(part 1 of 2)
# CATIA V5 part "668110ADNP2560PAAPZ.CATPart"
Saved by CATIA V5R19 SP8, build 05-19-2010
Part number: 668110 ADNP-25-60-P-A---A-P-(Z)
Definition: Cadenas PARTsolutions
Description: NT
Property "NN": "ADNP-A-P-(Z)"
Property "NT": "Normzylinder"
Property "NB": "668110 ADNP-25-60-P-A---A-P-(Z)"
Property "NBSYN": "$TNR. $TYP.-$HUB.-$ED.---A-P-(Z)"
Property "LINA": "668110 ADNP-25-60-P-A---A-P-(Z)"
Property "TNR": "668110"
Property "TYP": "ADNP-25"
Property "AUSF": "ADNP"
Property "KDM": "25"
Property "BG": "19.500"
Property "VERS": "1"
Property "HUB": "60.00000"
Property "THC": "'A','I'"
Property "ED": "P-A"
Property "A": "16.000"
Property "A1": "16.000"
Property "AF": "14.000"
Property "AF1": "0.000"
Property "AF2": "12.000"
Property "AF3": "14.000"
Property "B": "22.000"
Property "B1": "18.000"
Property "BG1": "15.000"
Property "D1": "9.000"
Property "D2": "9.000"
Property "D3": "4.100"
Property "D4": "14.000"
Property "D5": "6.000"
Property "D6": "M5"
Property "D7": "5.000"
Property "D8": "3.800"
Property "D9": "6.000"
Property "E": "39.500"
Property "EE": "M5"
Property "EEN": "5.000"
Property "EE1": "M5"
Property "J": "12.000"
Property "J1": "2.600"
Property "J11": "2.600"
Property "J2": "0.000"
Property "KF": "10-32 UNF-2B"
Property "KF1": "-"
Property "KF2": "10-32 UNF-2B"
Property "KF3": "10-32 UNF-2B"
Property "KK": "5/16-24 UNF-2A"
Property "KK1": "5/16-24 UNF-2A"
Property "L1": "2.600"
Property "L2": "39.000"
Property "L3": "2.100"
Property "L4": "4.800"
Property "L5": "5.000"
Property "L6": "53.000"
Property "L7": "22.000"
Property "L8": "2.000"
Property "L9": "2.000"
Property "L10": "5.000"
Property "L11": "2.600"
Property "MF": "8.000"
Property "MM": "10.000"
Property "MM1": "10.000"
Property "PL": "6.000"
Property "RT": "M5"
Property "RTN": "5"
Property "RTNK": "4.134"
Property "SF": "11/32"
Property "SF1": "11/32"
Property "SW": "9.000"
Property "TG": "26.000"
Property "VD": "6.000"
Property "VD1": "5.200"
Property "WH": "5.700"
Property "WH1": "11.650"
Property "WL": "4.200"
Property "WL1": "4.200"
Property "Y1": "0.300"
Property "Y2": "0.500"
Property "ZJ": "44.700"
Property "ZM": "50.400"
Property "RU": "28.200"
Property "R1": "11.700"
Property "R2": "0.800"
Property "RA": "0.000"
Property "RB1": "5.400"
Property "RB2": "6.800"
Property "RT1": "3.400"
Property "DSK": "8.000"
Property "MDK": "10.000"
Property "MK": "6.000"
Property "MT": "3.000"
Property "MS": "5.000"
Property "RUB": "0.400"
Property "KFN": "6.000"
Property "KFK": "4.917"
Property "B111": "11.500"
Property "B11": "1.000"
Property "B2": "6.500"
Property "B3": "10.500"
Property "B4": "4.600"
Property "B5": "4.400"
Property "B6": "7.500"
Property "B7": "19.500"
Property "B8": "5.000"
Property "B9": "7.000"
Property "B10": "8.400"
Property "W": "0.400"
Property "S": "7.000"
Property "LA": "0.000"
Property "LA1": "0.000"
Property "LA2": "5.500"
Property "LA3": "11.000"
Property "LA31": "11.000"
Property "LA4": "0.000"
Property "LA5": "11.000"
Property "LA6": "5.500"
Property "RR": "4.100"
Property "LA7": "0.000"
Property "LA8": "0.000"
Property "LA9": "0.000"
Property "LA10": "0.000"
Property "ES": "0.000"
Property "SS": "0.000"
Property "TS": "0.000"
Property "WS": "0.000"
Property "DK": "0.000"
Property "KS": "0.000"
Property "TT": "-"
Property "R8": "-"
Property "S1": "-"
Property "S2S20": "-"
Property "Q": "-"
Property "X": "60.000"
Property "VENDOR": "FESTO"
Property "SUPPLIER": "FESTO"
Property "ARTICLENO": "NB"
Property "BOMINFO": "LINA"
Property "CREATOR": "CADENAS GmbH"
Bounding box of the stored display mesh (mm): x -19.75 to 19.75, y -19.75 to 19.75, z -99 to 0
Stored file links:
  C:\Users\Schrotter\Desktop\Neuer Ordner (2)\668110ADNP2560PAAPZ.CATPart
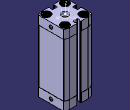
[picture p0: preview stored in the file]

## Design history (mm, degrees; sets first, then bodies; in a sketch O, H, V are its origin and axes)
AxisSystem1: origin (0, 0, 0), X (1, 0, 0), Y (0, 1, 0), Z (0, 0, 1)
Set1
  Point1: (0, 0, 0)
  Point2: (1, 0, 0)
  Point3: (0, 1, 0)
  Plane1: type 3Points, Element1 Point1, Element2 Point2, Element3 Point3
  Point4: (0, 0, -12)
  Point5: (1, 0, -12)
  Point6: (0, 1, -12)
  Plane2: type 3Points, Element1 Point4, Element2 Point5, Element3 Point6
  Point7: (0, 0, 0)
  Point8: (1, 0, 0)
  Point9: (0, 0, -1)
  Plane3: type 3Points, Element1 Point7, Element2 Point8, Element3 Point9
  Point10: (0, 0, 0)
  Point11: (1, 0, 0)
  Point12: (0, 0, -1)
  Plane4: type 3Points, Element1 Point10, Element2 Point11, Element3 Point12
  Point13: (0, 0, 0)
  Point14: (0, 0, -1)
  Point15: (0, 1, 0)
  Plane5: type 3Points, Element1 Point13, Element2 Point14, Element3 Point15
  Point16: (0, 0, 0)
  Point17: (0, 0, -1)
  Point18: (0, 1, 0)
  Plane6: type 3Points, Element1 Point16, Element2 Point17, Element3 Point18
  Point19: (13, 0, 0)
  Point20: (13, 0, -1)
  Point21: (13, 1, 0)
  Plane7: type 3Points, Element1 Point19, Element2 Point20, Element3 Point21
  Point22: (13, 0, 0)
  Point23: (13, 0, -1)
  Point24: (13, 1, 0)
  Plane8: type 3Points, Element1 Point22, Element2 Point23, Element3 Point24
  Point25: (13, 0, 0)
  Point26: (13, 0, -1)
  Point27: (13, 1, 0)
  Plane9: type 3Points, Element1 Point25, Element2 Point26, Element3 Point27
  Point28: (13, 0, 0)
  Point29: (13, 0, -1)
  Point30: (13, 1, 0)
  Plane10: type 3Points, Element1 Point28, Element2 Point29, Element3 Point30
  Point31: (-13, 0, 0)
  Point32: (-13, 0, -1)
  Point33: (-13, 1, 0)
  Plane11: type 3Points, Element1 Point31, Element2 Point32, Element3 Point33
  Point34: (-13, 0, 0)
  Point35: (-13, 0, -1)
  Point36: (-13, 1, 0)
  Plane12: type 3Points, Element1 Point34, Element2 Point35, Element3 Point36
  Point37: (-13, 0, 0)
  Point38: (-13, 0, -1)
  Point39: (-13, 1, 0)
  Plane13: type 3Points, Element1 Point37, Element2 Point38, Element3 Point39
  Point40: (-13, 0, 0)
  Point41: (-13, 0, -1)
  Point42: (-13, 1, 0)
  Plane14: type 3Points, Element1 Point40, Element2 Point41, Element3 Point42
  Point43: (-13, 0, 0)
  Point44: (-13, 0, -1)
  Point45: (-13, 1, 0)
  Plane15: type 3Points, Element1 Point43, Element2 Point44, Element3 Point45
  Point46: (-13, 0, 0)
  Point47: (-13, 0, -1)
  Point48: (-13, 1, 0)
  Plane16: type 3Points, Element1 Point46, Element2 Point47, Element3 Point48
  Point49: (13, 0, 0)
  Point50: (13, 0, -1)
  Point51: (13, 1, 0)
  Plane17: type 3Points, Element1 Point49, Element2 Point50, Element3 Point51
  Point52: (13, 0, 0)
  Point53: (13, 0, -1)
  Point54: (13, 1, 0)
  Plane18: type 3Points, Element1 Point52, Element2 Point53, Element3 Point54
  Point55: (-13, 0, 0)
  Point56: (-13, 0, -1)
  Point57: (-13, 1, 0)
  Plane19: type 3Points, Element1 Point55, Element2 Point56, Element3 Point57
  Point58: (-13, 0, 0)
  Point59: (-13, 0, -1)
  Point60: (-13, 1, 0)
  Plane20: type 3Points, Element1 Point58, Element2 Point59, Element3 Point60
  Point61: (13, 0, 0)
  Point62: (13, 0, -1)
  Point63: (13, 1, 0)
  Plane21: type 3Points, Element1 Point61, Element2 Point62, Element3 Point63
  Point64: (13, 0, 0)
  Point65: (13, 0, -1)
  Point66: (13, 1, 0)
  Plane22: type 3Points, Element1 Point64, Element2 Point65, Element3 Point66
  Point67: (0, 0, 0)
  Point68: (1, 0, 0)
  Point69: (0, 1, 0)
  Plane23: type 3Points, Element1 Point67, Element2 Point68, Element3 Point69
  Point70: (0, 0, 0)
  Point71: (1, 0, 0)
  Point72: (0, 1, 0)
  Plane24: type 3Points, Element1 Point70, Element2 Point71, Element3 Point72
  Point73: (0, 0, 0)
  Point74: (1, 0, 0)
  Point75: (0, 1, 0)
  Plane25: type 3Points, Element1 Point73, Element2 Point74, Element3 Point75
  Point76: (0, 0, 0)
  Point77: (1, 0, 0)
  Point78: (0, 1, 0)
  Plane26: type 3Points, Element1 Point76, Element2 Point77, Element3 Point78
  Point79: (0, 0, -99)
  Point80: (1, 0, -99)
  Point81: (0, 1, -99)
  Plane27: type 3Points, Element1 Point79, Element2 Point80, Element3 Point81
  Point82: (0, 0, -99)
  Point83: (1, 0, -99)
  Point84: (0, 1, -99)
  Plane28: type 3Points, Element1 Point82, Element2 Point83, Element3 Point84
  Point85: (0, 0, -99)
  Point86: (1, 0, -99)
  Point87: (0, 1, -99)
  Plane29: type 3Points, Element1 Point85, Element2 Point86, Element3 Point87
  Point88: (0, 0, -99)
  Point89: (1, 0, -99)
  Point90: (0, 1, -99)
  Plane30: type 3Points, Element1 Point88, Element2 Point89, Element3 Point90
  Point91: (13, 0, 0)
  Point92: (13, 0, -1)
  Point93: (13, 1, 0)
  Plane31: type 3Points, Element1 Point91, Element2 Point92, Element3 Point93
  Point94: (13, 0, 0)
  Point95: (13, 0, -1)
  Point96: (13, 1, 0)
  Plane32: type 3Points, Element1 Point94, Element2 Point95, Element3 Point96
  Point97: (-13, 0, 0)
  Point98: (-13, 0, -1)
  Point99: (-13, 1, 0)
  Plane33: type 3Points, Element1 Point97, Element2 Point98, Element3 Point99
  Point100: (-13, 0, 0)
  Point101: (-13, 0, -1)
  Point102: (-13, 1, 0)
  Plane34: type 3Points, Element1 Point100, Element2 Point101, Element3 Point102
Body1 (main body)
  Sketch1 on Plane1, origin (0, 0, 0), H (1, 0, 0), V (0, 1, 0)
    point P1 (-19.75, 17.1828)
    point P2 (-19.75, 3.1)
    line L1 (-19.75, 17.1828) -> (-19.75, 3.1)
    point P3 (-19.75, 3.1)
    point P4 (-19.35, 2.7)
    arc A1 centre (-19.35, 3.1) radius 0.4 from (-19.75, 3.1) to (-19.35, 2.7) ccw
    point P5 (-19.35, 2.7)
    point P6 (-17.7, 2.7)
    line L2 (-19.35, 2.7) -> (-17.7, 2.7)
    point P7 (-17.7, 2.7)
    point P8 (-17.5, 2.9)
    arc A2 centre (-17.7, 2.9) radius 0.2 from (-17.7, 2.7) to (-17.5, 2.9) ccw
    point P9 (-17.5, 2.9)
    point P10 (-17.5, 3.2)
    line L3 (-17.5, 2.9) -> (-17.5, 3.2)
    point P11 (-17.3, 3.4)
    point P12 (-17.5, 3.2)
    arc A3 centre (-17.3, 3.2) radius 0.2 from (-17.3, 3.4) to (-17.5, 3.2) ccw
    point P13 (-17.3, 3.4)
    point P14 (-14.5, 3.4)
    line L4 (-17.3, 3.4) -> (-14.5, 3.4)
    point P15 (-14.1, 3)
    point P16 (-14.5, 3.4)
    arc A4 centre (-14.5, 3) radius 0.4 from (-14.1, 3) to (-14.5, 3.4) ccw
    point P17 (-14.1, 3)
    point P18 (-14.1, -3)
    line L5 (-14.1, 3) -> (-14.1, -3)
    point P19 (-14.5, -3.4)
    point P20 (-14.1, -3)
    arc A5 centre (-14.5, -3) radius 0.4 from (-14.5, -3.4) to (-14.1, -3) ccw
    point P21 (-14.5, -3.4)
    point P22 (-17.3, -3.4)
    line L6 (-14.5, -3.4) -> (-17.3, -3.4)
    point P23 (-17.5, -3.2)
    point P24 (-17.3, -3.4)
    arc A6 centre (-17.3, -3.2) radius 0.2 from (-17.5, -3.2) to (-17.3, -3.4) ccw
    point P25 (-17.5, -3.2)
    point P26 (-17.5, -2.9)
    line L7 (-17.5, -3.2) -> (-17.5, -2.9)
    point P27 (-17.5, -2.9)
    point P28 (-17.7, -2.7)
    arc A7 centre (-17.7, -2.9) radius 0.2 from (-17.5, -2.9) to (-17.7, -2.7) ccw
    point P29 (-17.7, -2.7)
    point P30 (-19.35, -2.7)
    line L8 (-17.7, -2.7) -> (-19.35, -2.7)
    point P31 (-19.35, -2.7)
    point P32 (-19.75, -3.1)
    arc A8 centre (-19.35, -3.1) radius 0.4 from (-19.35, -2.7) to (-19.75, -3.1) ccw
    point P33 (-19.75, -3.1)
    point P34 (-19.75, -17.1828)
    line L9 (-19.75, -3.1) -> (-19.75, -17.1828)
    point P35 (-19.75, -17.1828)
    point P36 (-19.3867, -17.8531)
    arc A9 centre (-18.95, -17.1828) radius 0.8 from (-19.75, -17.1828) to (-19.3867, -17.8531) ccw
    point P37 (-19.3867, -17.8531)
    point P38 (-13, -19.75)
    arc A10 centre (-13, -8.05) radius 11.7 from (-19.3867, -17.8531) to (-13, -19.75) ccw
    point P39 (-13, -19.75)
    point P40 (-3.1, -19.75)
    line L10 (-13, -19.75) -> (-3.1, -19.75)
    point P41 (-3.1, -19.75)
    point P42 (-2.7, -19.35)
    arc A11 centre (-3.1, -19.35) radius 0.4 from (-3.1, -19.75) to (-2.7, -19.35) ccw
    point P43 (-2.7, -19.35)
    point P44 (-2.7, -17.7)
    line L11 (-2.7, -19.35) -> (-2.7, -17.7)
    point P45 (-2.7, -17.7)
    point P46 (-2.9, -17.5)
    arc A12 centre (-2.9, -17.7) radius 0.2 from (-2.7, -17.7) to (-2.9, -17.5) ccw
    point P47 (-2.9, -17.5)
    point P48 (-3.2, -17.5)
    line L12 (-2.9, -17.5) -> (-3.2, -17.5)
    point P49 (-3.4, -17.3)
    point P50 (-3.2, -17.5)
    arc A13 centre (-3.2, -17.3) radius 0.2 from (-3.4, -17.3) to (-3.2, -17.5) ccw
    point P51 (-3.4, -17.3)
    point P52 (-3.4, -14.5)
    line L13 (-3.4, -17.3) -> (-3.4, -14.5)
    point P53 (-3, -14.1)
    point P54 (-3.4, -14.5)
    arc A14 centre (-3, -14.5) radius 0.4 from (-3, -14.1) to (-3.4, -14.5) ccw
    point P55 (-3, -14.1)
    point P56 (3, -14.1)
    line L14 (-3, -14.1) -> (3, -14.1)
    point P57 (3.4, -14.5)
    point P58 (3, -14.1)
    arc A15 centre (3, -14.5) radius 0.4 from (3.4, -14.5) to (3, -14.1) ccw
    point P59 (3.4, -14.5)
    point P60 (3.4, -17.3)
    line L15 (3.4, -14.5) -> (3.4, -17.3)
    point P61 (3.2, -17.5)
    point P62 (3.4, -17.3)
    arc A16 centre (3.2, -17.3) radius 0.2 from (3.2, -17.5) to (3.4, -17.3) ccw
    point P63 (3.2, -17.5)
    point P64 (2.9, -17.5)
    line L16 (3.2, -17.5) -> (2.9, -17.5)
    point P65 (2.9, -17.5)
    point P66 (2.7, -17.7)
    arc A17 centre (2.9, -17.7) radius 0.2 from (2.9, -17.5) to (2.7, -17.7) ccw
    point P67 (2.7, -17.7)
    point P68 (2.7, -19.35)
    line L17 (2.7, -17.7) -> (2.7, -19.35)
    point P69 (2.7, -19.35)
    point P70 (3.1, -19.75)
    arc A18 centre (3.1, -19.35) radius 0.4 from (2.7, -19.35) to (3.1, -19.75) ccw
    point P71 (3.1, -19.75)
    point P72 (13, -19.75)
    line L18 (3.1, -19.75) -> (13, -19.75)
    point P73 (13, -19.75)
    point P74 (19.3867, -17.8531)
    arc A19 centre (13, -8.05) radius 11.7 from (13, -19.75) to (19.3867, -17.8531) ccw
    point P75 (19.3867, -17.8531)
    point P76 (19.75, -17.1828)
    arc A20 centre (18.95, -17.1828) radius 0.8 from (19.3867, -17.8531) to (19.75, -17.1828) ccw
    point P77 (19.75, -17.1828)
    point P78 (19.75, 17.1828)
    line L19 (19.75, -17.1828) -> (19.75, 17.1828)
    point P79 (19.75, 17.1828)
    point P80 (19.3867, 17.8531)
    arc A21 centre (18.95, 17.1828) radius 0.8 from (19.75, 17.1828) to (19.3867, 17.8531) ccw
    point P81 (19.3867, 17.8531)
    point P82 (13, 19.75)
    arc A22 centre (13, 8.05) radius 11.7 from (19.3867, 17.8531) to (13, 19.75) ccw
    point P83 (13, 19.75)
    point P84 (3.1, 19.75)
    line L20 (13, 19.75) -> (3.1, 19.75)
    point P85 (3.1, 19.75)
    point P86 (2.7, 19.35)
    arc A23 centre (3.1, 19.35) radius 0.4 from (3.1, 19.75) to (2.7, 19.35) ccw
    point P87 (2.7, 19.35)
    point P88 (2.7, 17.7)
    line L21 (2.7, 19.35) -> (2.7, 17.7)
    point P89 (2.7, 17.7)
    point P90 (2.9, 17.5)
    arc A24 centre (2.9, 17.7) radius 0.2 from (2.7, 17.7) to (2.9, 17.5) ccw
    point P91 (2.9, 17.5)
    point P92 (3.2, 17.5)
    line L22 (2.9, 17.5) -> (3.2, 17.5)
    point P93 (3.4, 17.3)
    point P94 (3.2, 17.5)
    arc A25 centre (3.2, 17.3) radius 0.2 from (3.4, 17.3) to (3.2, 17.5) ccw
    point P95 (3.4, 17.3)
    point P96 (3.4, 14.5)
    line L23 (3.4, 17.3) -> (3.4, 14.5)
    point P97 (3, 14.1)
    point P98 (3.4, 14.5)
    arc A26 centre (3, 14.5) radius 0.4 from (3, 14.1) to (3.4, 14.5) ccw
    point P99 (3, 14.1)
    point P100 (-3, 14.1)
    line L24 (3, 14.1) -> (-3, 14.1)
    point P101 (-3.4, 14.5)
    point P102 (-3, 14.1)
    arc A27 centre (-3, 14.5) radius 0.4 from (-3.4, 14.5) to (-3, 14.1) ccw
    point P103 (-3.4, 14.5)
    point P104 (-3.4, 17.3)
    line L25 (-3.4, 14.5) -> (-3.4, 17.3)
    point P105 (-3.2, 17.5)
    point P106 (-3.4, 17.3)
    arc A28 centre (-3.2, 17.3) radius 0.2 from (-3.2, 17.5) to (-3.4, 17.3) ccw
    point P107 (-3.2, 17.5)
    point P108 (-2.9, 17.5)
    line L26 (-3.2, 17.5) -> (-2.9, 17.5)
    point P109 (-2.9, 17.5)
    point P110 (-2.7, 17.7)
    arc A29 centre (-2.9, 17.7) radius 0.2 from (-2.9, 17.5) to (-2.7, 17.7) ccw
    point P111 (-2.7, 17.7)
    point P112 (-2.7, 19.35)
    line L27 (-2.7, 17.7) -> (-2.7, 19.35)
    point P113 (-2.7, 19.35)
    point P114 (-3.1, 19.75)
    arc A30 centre (-3.1, 19.35) radius 0.4 from (-2.7, 19.35) to (-3.1, 19.75) ccw
    point P115 (-3.1, 19.75)
    point P116 (-13, 19.75)
    line L28 (-3.1, 19.75) -> (-13, 19.75)
    point P117 (-13, 19.75)
    point P118 (-19.3867, 17.8531)
    arc A31 centre (-13, 8.05) radius 11.7 from (-13, 19.75) to (-19.3867, 17.8531) ccw
    point P119 (-19.3867, 17.8531)
    point P120 (-19.75, 17.1828)
    arc A32 centre (-18.95, 17.1828) radius 0.8 from (-19.3867, 17.8531) to (-19.75, 17.1828) ccw
    coincidence: P1 P120, P2 P3, P4 P5, P6 P7, P8 P9, P10 P12, P11 P13, P14 P16, P15 P17, P18 P20, P19 P21, P22 P24, P23 P25, P26 P27, P28 P29, P30 P31, P32 P33, P34 P35, P36 P37, P38 P39, P40 P41, P42 P43, P44 P45, P46 P47, P48 P50, P49 P51, P52 P54, P53 P55, P56 P58, P57 P59, P60 P62, P61 P63, P64 P65, P66 P67, P68 P69, P70 P71, P72 P73, P74 P75, P76 P77, P78 P79, P80 P81, P82 P83, P84 P85, P86 P87, P88 P89, P90 P91, P92 P94, P93 P95, P96 P98, P97 P99, P100 P102, P101 P103, P104 P106, P105 P107, P108 P109, P110 P111, P112 P113, P114 P115, P116 P117, P118 P119
  Pad1: profile Sketch1, direction (0, 0, -1), length 99
  Sketch2 on Plane2, origin (0, 0, -12), H (1, 0, 0), V (0, 1, 0)
    point P1 (-39.5, -39.5)
    point P2 (39.5, -39.5)
    line L1 (-39.5, -39.5) -> (39.5, -39.5)
    point P3 (39.5, -39.5)
    point P4 (39.5, 39.5)
    line L2 (39.5, -39.5) -> (39.5, 39.5)
    point P5 (39.5, 39.5)
    point P6 (-39.5, 39.5)
    line L3 (39.5, 39.5) -> (-39.5, 39.5)
    point P7 (-39.5, 39.5)
    point P8 (-39.5, -39.5)
    line L4 (-39.5, 39.5) -> (-39.5, -39.5)
    point P9 (-19.5, 17.0909)
    point P10 (-19.5, 3.1)
    line L5 (-19.5, 17.0909) -> (-19.5, 3.1)
    point P11 (-19.5, 3.1)
    point P12 (-19.1, 2.7)
    arc A1 centre (-19.1, 3.1) radius 0.4 from (-19.5, 3.1) to (-19.1, 2.7) ccw
    point P13 (-19.1, 2.7)
    point P14 (-17.7, 2.7)
    line L6 (-19.1, 2.7) -> (-17.7, 2.7)
    point P15 (-17.7, 2.7)
    point P16 (-17.5, 2.9)
    arc A2 centre (-17.7, 2.9) radius 0.2 from (-17.7, 2.7) to (-17.5, 2.9) ccw
    point P17 (-17.5, 2.9)
    point P18 (-17.5, 3.2)
    line L7 (-17.5, 2.9) -> (-17.5, 3.2)
    point P19 (-17.3, 3.4)
    point P20 (-17.5, 3.2)
    arc A3 centre (-17.3, 3.2) radius 0.2 from (-17.3, 3.4) to (-17.5, 3.2) ccw
    point P21 (-17.3, 3.4)
    point P22 (-14.5, 3.4)
    line L8 (-17.3, 3.4) -> (-14.5, 3.4)
    point P23 (-14.1, 3)
    point P24 (-14.5, 3.4)
    arc A4 centre (-14.5, 3) radius 0.4 from (-14.1, 3) to (-14.5, 3.4) ccw
    point P25 (-14.1, 3)
    point P26 (-14.1, -3)
    line L9 (-14.1, 3) -> (-14.1, -3)
    point P27 (-14.5, -3.4)
    point P28 (-14.1, -3)
    arc A5 centre (-14.5, -3) radius 0.4 from (-14.5, -3.4) to (-14.1, -3) ccw
    point P29 (-14.5, -3.4)
    point P30 (-17.3, -3.4)
    line L10 (-14.5, -3.4) -> (-17.3, -3.4)
    point P31 (-17.5, -3.2)
    point P32 (-17.3, -3.4)
    arc A6 centre (-17.3, -3.2) radius 0.2 from (-17.5, -3.2) to (-17.3, -3.4) ccw
    point P33 (-17.5, -3.2)
    point P34 (-17.5, -2.9)
    line L11 (-17.5, -3.2) -> (-17.5, -2.9)
    point P35 (-17.5, -2.9)
    point P36 (-17.7, -2.7)
    arc A7 centre (-17.7, -2.9) radius 0.2 from (-17.5, -2.9) to (-17.7, -2.7) ccw
    point P37 (-17.7, -2.7)
    point P38 (-19.1, -2.7)
    line L12 (-17.7, -2.7) -> (-19.1, -2.7)
    point P39 (-19.1, -2.7)
    point P40 (-19.5, -3.1)
    arc A8 centre (-19.1, -3.1) radius 0.4 from (-19.1, -2.7) to (-19.5, -3.1) ccw
    point P41 (-19.5, -3.1)
    point P42 (-19.5, -17.0909)
    line L13 (-19.5, -3.1) -> (-19.5, -17.0909)
    point P43 (-19.5, -17.0909)
    point P44 (-19.1183, -17.7728)
    arc A9 centre (-18.7, -17.0909) radius 0.8 from (-19.5, -17.0909) to (-19.1183, -17.7728) ccw
    point P45 (-19.1183, -17.7728)
    point P46 (-13, -19.5)
    arc A10 centre (-13, -7.8) radius 11.7 from (-19.1183, -17.7728) to (-13, -19.5) ccw
    point P47 (-13, -19.5)
    point P48 (-3.1, -19.5)
    line L14 (-13, -19.5) -> (-3.1, -19.5)
    point P49 (-3.1, -19.5)
    point P50 (-2.7, -19.1)
    arc A11 centre (-3.1, -19.1) radius 0.4 from (-3.1, -19.5) to (-2.7, -19.1) ccw
    point P51 (-2.7, -19.1)
    point P52 (-2.7, -17.7)
    line L15 (-2.7, -19.1) -> (-2.7, -17.7)
    point P53 (-2.7, -17.7)
    point P54 (-2.9, -17.5)
    arc A12 centre (-2.9, -17.7) radius 0.2 from (-2.7, -17.7) to (-2.9, -17.5) ccw
    point P55 (-2.9, -17.5)
    point P56 (-3.2, -17.5)
    line L16 (-2.9, -17.5) -> (-3.2, -17.5)
    point P57 (-3.4, -17.3)
    point P58 (-3.2, -17.5)
    arc A13 centre (-3.2, -17.3) radius 0.2 from (-3.4, -17.3) to (-3.2, -17.5) ccw
    point P59 (-3.4, -17.3)
    point P60 (-3.4, -14.5)
    line L17 (-3.4, -17.3) -> (-3.4, -14.5)
    point P61 (-3, -14.1)
    point P62 (-3.4, -14.5)
    arc A14 centre (-3, -14.5) radius 0.4 from (-3, -14.1) to (-3.4, -14.5) ccw
    point P63 (-3, -14.1)
    point P64 (3, -14.1)
    line L18 (-3, -14.1) -> (3, -14.1)
    point P65 (3.4, -14.5)
    point P66 (3, -14.1)
    arc A15 centre (3, -14.5) radius 0.4 from (3.4, -14.5) to (3, -14.1) ccw
    point P67 (3.4, -14.5)
    point P68 (3.4, -17.3)
    line L19 (3.4, -14.5) -> (3.4, -17.3)
    point P69 (3.2, -17.5)
    point P70 (3.4, -17.3)
    arc A16 centre (3.2, -17.3) radius 0.2 from (3.2, -17.5) to (3.4, -17.3) ccw
    point P71 (3.2, -17.5)
    point P72 (2.9, -17.5)
    line L20 (3.2, -17.5) -> (2.9, -17.5)
    point P73 (2.9, -17.5)
    point P74 (2.7, -17.7)
    arc A17 centre (2.9, -17.7) radius 0.2 from (2.9, -17.5) to (2.7, -17.7) ccw
    point P75 (2.7, -17.7)
    point P76 (2.7, -19.1)
    line L21 (2.7, -17.7) -> (2.7, -19.1)
    point P77 (2.7, -19.1)
    point P78 (3.1, -19.5)
    arc A18 centre (3.1, -19.1) radius 0.4 from (2.7, -19.1) to (3.1, -19.5) ccw
    point P79 (3.1, -19.5)
    point P80 (13, -19.5)
    line L22 (3.1, -19.5) -> (13, -19.5)
    point P81 (13, -19.5)
    point P82 (19.1183, -17.7728)
    arc A19 centre (13, -7.8) radius 11.7 from (13, -19.5) to (19.1183, -17.7728) ccw
    point P83 (19.1183, -17.7728)
    point P84 (19.5, -17.0909)
    arc A20 centre (18.7, -17.0909) radius 0.8 from (19.1183, -17.7728) to (19.5, -17.0909) ccw
    point P85 (19.5, -17.0909)
    point P86 (19.5, 17.0909)
    line L23 (19.5, -17.0909) -> (19.5, 17.0909)
    point P87 (19.5, 17.0909)
    point P88 (19.1183, 17.7728)
    arc A21 centre (18.7, 17.0909) radius 0.8 from (19.5, 17.0909) to (19.1183, 17.7728) ccw
    point P89 (19.1183, 17.7728)
    point P90 (13, 19.5)
    arc A22 centre (13, 7.8) radius 11.7 from (19.1183, 17.7728) to (13, 19.5) ccw
    point P91 (13, 19.5)
    point P92 (3.1, 19.5)
    line L24 (13, 19.5) -> (3.1, 19.5)
    point P93 (3.1, 19.5)
    point P94 (2.7, 19.1)
    arc A23 centre (3.1, 19.1) radius 0.4 from (3.1, 19.5) to (2.7, 19.1) ccw
    point P95 (2.7, 19.1)
    point P96 (2.7, 17.7)
    line L25 (2.7, 19.1) -> (2.7, 17.7)
    point P97 (2.7, 17.7)
    point P98 (2.9, 17.5)
    arc A24 centre (2.9, 17.7) radius 0.2 from (2.7, 17.7) to (2.9, 17.5) ccw
    point P99 (2.9, 17.5)
    point P100 (3.2, 17.5)
    line L26 (2.9, 17.5) -> (3.2, 17.5)
    point P101 (3.4, 17.3)
    point P102 (3.2, 17.5)
    arc A25 centre (3.2, 17.3) radius 0.2 from (3.4, 17.3) to (3.2, 17.5) ccw
    point P103 (3.4, 17.3)
    point P104 (3.4, 14.5)
    line L27 (3.4, 17.3) -> (3.4, 14.5)
    point P105 (3, 14.1)
    point P106 (3.4, 14.5)
    arc A26 centre (3, 14.5) radius 0.4 from (3, 14.1) to (3.4, 14.5) ccw
    point P107 (3, 14.1)
    point P108 (-3, 14.1)
    line L28 (3, 14.1) -> (-3, 14.1)
    point P109 (-3.4, 14.5)
    point P110 (-3, 14.1)
    arc A27 centre (-3, 14.5) radius 0.4 from (-3.4, 14.5) to (-3, 14.1) ccw
    point P111 (-3.4, 14.5)
    point P112 (-3.4, 17.3)
    line L29 (-3.4, 14.5) -> (-3.4, 17.3)
    point P113 (-3.2, 17.5)
    point P114 (-3.4, 17.3)
    arc A28 centre (-3.2, 17.3) radius 0.2 from (-3.2, 17.5) to (-3.4, 17.3) ccw
    point P115 (-3.2, 17.5)
    point P116 (-2.9, 17.5)
    line L30 (-3.2, 17.5) -> (-2.9, 17.5)
    point P117 (-2.9, 17.5)
    point P118 (-2.7, 17.7)
    arc A29 centre (-2.9, 17.7) radius 0.2 from (-2.9, 17.5) to (-2.7, 17.7) ccw
    point P119 (-2.7, 17.7)
    point P120 (-2.7, 19.1)
    line L31 (-2.7, 17.7) -> (-2.7, 19.1)
    point P121 (-2.7, 19.1)
    point P122 (-3.1, 19.5)
    arc A30 centre (-3.1, 19.1) radius 0.4 from (-2.7, 19.1) to (-3.1, 19.5) ccw
    point P123 (-3.1, 19.5)
    point P124 (-13, 19.5)
    line L32 (-3.1, 19.5) -> (-13, 19.5)
    point P125 (-13, 19.5)
    point P126 (-19.1183, 17.7728)
    arc A31 centre (-13, 7.8) radius 11.7 from (-13, 19.5) to (-19.1183, 17.7728) ccw
    point P127 (-19.1183, 17.7728)
    point P128 (-19.5, 17.0909)
    arc A32 centre (-18.7, 17.0909) radius 0.8 from (-19.1183, 17.7728) to (-19.5, 17.0909) ccw
    coincidence: P1 P8, P2 P3, P4 P5, P6 P7, P9 P128, P10 P11, P12 P13, P14 P15, P16 P17, P18 P20, P19 P21, P22 P24, P23 P25, P26 P28, P27 P29, P30 P32, P31 P33, P34 P35, P36 P37, P38 P39, P40 P41, P42 P43, P44 P45, P46 P47, P48 P49, P50 P51, P52 P53, P54 P55, P56 P58, P57 P59, P60 P62, P61 P63, P64 P66, P65 P67, P68 P70, P69 P71, P72 P73, P74 P75, P76 P77, P78 P79, P80 P81, P82 P83, P84 P85, P86 P87, P88 P89, P90 P91, P92 P93, P94 P95, P96 P97, P98 P99, P100 P102, P101 P103, P104 P106, P105 P107, P108 P110, P109 P111, P112 P114, P113 P115, P116 P117, P118 P119, P120 P121, P122 P123, P124 P125, P126 P127
  Pocket1: profile Sketch2, direction (0, 0, -1), length 75
  Sketch3 on Plane3, origin (0, 0, 0), H (1, 0, 0), V (0, 0, -1)
    point P1 (8.75, 6)
    point P2 (8.75, 8.067)
    line L1 (8.75, 6) -> (8.75, 8.067)
    point P3 (8.75, 8.067)
    point P4 (19.317, 8.067)
    line L2 (8.75, 8.067) -> (19.317, 8.067)
    point P5 (19.317, 8.067)
    point P6 (19.75, 8.5)
    line L3 (19.317, 8.067) -> (19.75, 8.5)
    point P7 (19.75, 8.5)
    point P8 (19.75, 6)
    line L4 (19.75, 8.5) -> (19.75, 6)
    point P9 (19.75, 6)
    point P10 (8.75, 6)
    line L5 (19.75, 6) -> (8.75, 6)
    point P11 (19.75, 6)
    point P12 (8.75, 6)
    axis line L6 (19.75, 6) -> (8.75, 6)
    coincidence: P1 P10, P2 P3, P4 P5, P6 P7, P8 P9
  Groove1: profile Sketch3, axis Sketch3.L6, angle 0, second angle 360
  Sketch4 on Plane4, origin (0, 0, 0), H (1, 0, 0), V (0, 0, -1)
    point P1 (8.75, 93)
    point P2 (8.75, 95.067)
    line L1 (8.75, 93) -> (8.75, 95.067)
    point P3 (8.75, 95.067)
    point P4 (19.317, 95.067)
    line L2 (8.75, 95.067) -> (19.317, 95.067)
    point P5 (19.317, 95.067)
    point P6 (19.75, 95.5)
    line L3 (19.317, 95.067) -> (19.75, 95.5)
    point P7 (19.75, 95.5)
    point P8 (19.75, 93)
    line L4 (19.75, 95.5) -> (19.75, 93)
    point P9 (19.75, 93)
    point P10 (8.75, 93)
    line L5 (19.75, 93) -> (8.75, 93)
    point P11 (19.75, 93)
    point P12 (8.75, 93)
    axis line L6 (19.75, 93) -> (8.75, 93)
    coincidence: P1 P10, P2 P3, P4 P5, P6 P7, P8 P9
  Groove2: profile Sketch4, axis Sketch4.L6, angle 0, second angle 360
  Sketch5 on Plane5, origin (0, 0, 0), H (0, 0, -1), V (0, 1, 0)
    point P1 (-12.2, 0)
    point P2 (-12.2, 5)
    line L1 (-12.2, 0) -> (-12.2, 5)
    point P3 (-12.2, 5)
    point P4 (20.75, 5)
    line L2 (-12.2, 5) -> (20.75, 5)
    point P5 (20.75, 5)
    point P6 (20.75, 12.5)
    line L3 (20.75, 5) -> (20.75, 12.5)
    point P7 (20.75, 12.5)
    point P8 (87, 12.5)
    line L4 (20.75, 12.5) -> (87, 12.5)
    point P9 (87, 12.5)
    point P10 (87, 0)
    line L5 (87, 12.5) -> (87, 0)
    point P11 (87, 0)
    point P12 (-12.2, 0)
    line L6 (87, 0) -> (-12.2, 0)
    point P13 (87, 0)
    point P14 (-12.2, 0)
    axis line L7 (87, 0) -> (-12.2, 0)
    coincidence: P1 P12, P2 P3, P4 P5, P6 P7, P8 P9, P10 P11
  Groove3: profile Sketch5, axis Sketch5.L7, angle 0, second angle 360
  Sketch6 on Plane6, origin (0, 0, 0), H (0, 0, -1), V (0, 1, 0)
    point P1 (96.9, 0)
    point P2 (96.9, 4.5)
    line L1 (96.9, 0) -> (96.9, 4.5)
    point P3 (96.9, 4.5)
    point P4 (99, 4.5)
    line L2 (96.9, 4.5) -> (99, 4.5)
    point P5 (99, 4.5)
    point P6 (99, 0)
    line L3 (99, 4.5) -> (99, 0)
    point P7 (99, 0)
    point P8 (96.9, 0)
    line L4 (99, 0) -> (96.9, 0)
    point P9 (99, 0)
    point P10 (96.9, 0)
    axis line L5 (99, 0) -> (96.9, 0)
    coincidence: P1 P8, P2 P3, P4 P5, P6 P7
  Groove4: profile Sketch6, axis Sketch6.L5, angle 0, second angle 360
  Sketch7 on Plane7, origin (13, 0, 0), H (0, 0, -1), V (0, 1, 0)
    point P1 (0, 13)
    point P2 (0, 18.75)
    line L1 (0, 13) -> (0, 18.75)
    point P3 (0, 18.75)
    point P4 (6.5, 18.75)
    line L2 (0, 18.75) -> (6.5, 18.75)
    point P5 (6.5, 18.75)
    point P6 (6.5, 16.5)
    line L3 (6.5, 18.75) -> (6.5, 16.5)
    point P7 (6.5, 16.5)
    point P8 (19.5, 16.5)
    line L4 (6.5, 16.5) -> (19.5, 16.5)
    point P9 (19.5, 16.5)
    point P10 (19.5, 13)
    line L5 (19.5, 16.5) -> (19.5, 13)
    point P11 (19.5, 13)
    point P12 (0, 13)
    line L6 (19.5, 13) -> (0, 13)
    point P13 (19.5, 13)
    point P14 (0, 13)
    axis line L7 (19.5, 13) -> (0, 13)
    coincidence: P1 P12, P2 P3, P4 P5, P6 P7, P8 P9, P10 P11
  Groove5: profile Sketch7, axis Sketch7.L7, angle 0, second angle 360
  Sketch8 on Plane8, origin (13, 0, 0), H (0, 0, -1), V (0, 1, 0)
    point P1 (0, 17.85)
    point P2 (0, 17.2)
    line L1 (0, 17.85) -> (0, 17.2)
    point P3 (0, 17.2)
    point P4 (0.7794, 16.75)
    line L2 (0, 17.2) -> (0.7794, 16.75)
    point P5 (0.7794, 16.75)
    point P6 (4.6, 16.75)
    line L3 (0.7794, 16.75) -> (4.6, 16.75)
    point P7 (4.6, 16.75)
    point P8 (4.6, 15.5)
    line L4 (4.6, 16.75) -> (4.6, 15.5)
    point P9 (4.6, 15.5)
    point P10 (5.033, 15.067)
    line L5 (4.6, 15.5) -> (5.033, 15.067)
    point P11 (5.033, 15.067)
    point P12 (19.5, 15.067)
    line L6 (5.033, 15.067) -> (19.5, 15.067)
    point P13 (19.5, 15.067)
    point P14 (19.5, 17.5)
    line L7 (19.5, 15.067) -> (19.5, 17.5)
    point P15 (19.5, 17.5)
    point P16 (6.5, 17.5)
    line L8 (19.5, 17.5) -> (6.5, 17.5)
    point P17 (6.5, 17.5)
    point P18 (6.5, 18.25)
    line L9 (6.5, 17.5) -> (6.5, 18.25)
    point P19 (6.5, 18.25)
    point P20 (0.4, 18.25)
    line L10 (6.5, 18.25) -> (0.4, 18.25)
    point P21 (0.4, 18.25)
    point P22 (0, 17.85)
    line L11 (0.4, 18.25) -> (0, 17.85)
    point P23 (19.5, 13)
    point P24 (0, 13)
    axis line L12 (19.5, 13) -> (0, 13)
    coincidence: P1 P22, P2 P3, P4 P5, P6 P7, P8 P9, P10 P11, P12 P13, P14 P15, P16 P17, P18 P19, P20 P21
  Shaft1: profile Sketch8, axis Sketch8.L12, angle 0, second angle 360
  Sketch9 on Plane9, origin (13, 0, 0), H (0, 0, -1), V (0, 1, 0)
    point P1 (79.5, -13)
    point P2 (79.5, -9.5)
    line L1 (79.5, -13) -> (79.5, -9.5)
    point P3 (79.5, -9.5)
    point P4 (92.5, -9.5)
    line L2 (79.5, -9.5) -> (92.5, -9.5)
    point P5 (92.5, -9.5)
    point P6 (92.5, -7.25)
    line L3 (92.5, -9.5) -> (92.5, -7.25)
    point P7 (92.5, -7.25)
    point P8 (99, -7.25)
    line L4 (92.5, -7.25) -> (99, -7.25)
    point P9 (99, -7.25)
    point P10 (99, -13)
    line L5 (99, -7.25) -> (99, -13)
    point P11 (99, -13)
    point P12 (79.5, -13)
    line L6 (99, -13) -> (79.5, -13)
    point P13 (99, -13)
    point P14 (79.5, -13)
    axis line L7 (99, -13) -> (79.5, -13)
    coincidence: P1 P12, P2 P3, P4 P5, P6 P7, P8 P9, P10 P11
  Groove6: profile Sketch9, axis Sketch9.L7, angle 0, second angle 360
  Sketch10 on Plane10, origin (13, 0, 0), H (0, 0, -1), V (0, 1, 0)
    point P1 (79.5, -10.933)
    point P2 (93.967, -10.933)
    line L1 (79.5, -10.933) -> (93.967, -10.933)
    point P3 (93.967, -10.933)
    point P4 (94.4, -10.5)
    line L2 (93.967, -10.933) -> (94.4, -10.5)
    point P5 (94.4, -10.5)
    point P6 (94.4, -9.25)
    line L3 (94.4, -10.5) -> (94.4, -9.25)
    point P7 (94.4, -9.25)
    point P8 (98.2206, -9.25)
    line L4 (94.4, -9.25) -> (98.2206, -9.25)
    point P9 (98.2206, -9.25)
    point P10 (99, -8.8)
    line L5 (98.2206, -9.25) -> (99, -8.8)
    point P11 (99, -8.8)
    point P12 (99, -8.15)
    line L6 (99, -8.8) -> (99, -8.15)
    point P13 (99, -8.15)
    point P14 (98.6, -7.75)
    line L7 (99, -8.15) -> (98.6, -7.75)
    point P15 (98.6, -7.75)
    point P16 (92.5, -7.75)
    line L8 (98.6, -7.75) -> (92.5, -7.75)
    point P17 (92.5, -7.75)
    point P18 (92.5, -8.5)
    line L9 (92.5, -7.75) -> (92.5, -8.5)
    point P19 (92.5, -8.5)
    point P20 (79.5, -8.5)
    line L10 (92.5, -8.5) -> (79.5, -8.5)
    point P21 (79.5, -8.5)
    point P22 (79.5, -10.933)
    line L11 (79.5, -8.5) -> (79.5, -10.933)
    point P23 (99, -13)
    point P24 (79.5, -13)
    axis line L12 (99, -13) -> (79.5, -13)
    coincidence: P1 P22, P2 P3, P4 P5, P6 P7, P8 P9, P10 P11, P12 P13, P14 P15, P16 P17, P18 P19, P20 P21
  Shaft2: profile Sketch10, axis Sketch10.L12, angle 0, second angle 360
  Sketch11 on Plane11, origin (-13, 0, 0), H (0, 0, -1), V (0, 1, 0)
    point P1 (0, -13)
    point P2 (0, -7.25)
    line L1 (0, -13) -> (0, -7.25)
    point P3 (0, -7.25)
    point P4 (6.5, -7.25)
    line L2 (0, -7.25) -> (6.5, -7.25)
    point P5 (6.5, -7.25)
    point P6 (6.5, -9.5)
    line L3 (6.5, -7.25) -> (6.5, -9.5)
    point P7 (6.5, -9.5)
    point P8 (19.5, -9.5)
    line L4 (6.5, -9.5) -> (19.5, -9.5)
    point P9 (19.5, -9.5)
    point P10 (19.5, -13)
    line L5 (19.5, -9.5) -> (19.5, -13)
    point P11 (19.5, -13)
    point P12 (0, -13)
    line L6 (19.5, -13) -> (0, -13)
    point P13 (49.5, -13)
    point P14 (0, -13)
    axis line L7 (49.5, -13) -> (0, -13)
    coincidence: P1 P12, P2 P3, P4 P5, P6 P7, P8 P9, P10 P11
  Groove7: profile Sketch11, axis Sketch11.L7, angle 0, second angle 360
  Sketch12 on Plane12, origin (-13, 0, 0), H (0, 0, -1), V (0, 1, 0)
    point P1 (79.5, 13)
    point P2 (79.5, 16.5)
    line L1 (79.5, 13) -> (79.5, 16.5)
    point P3 (79.5, 16.5)
    point P4 (92.5, 16.5)
    line L2 (79.5, 16.5) -> (92.5, 16.5)
    point P5 (92.5, 16.5)
    point P6 (92.5, 18.75)
    line L3 (92.5, 16.5) -> (92.5, 18.75)
    point P7 (92.5, 18.75)
    point P8 (99, 18.75)
    line L4 (92.5, 18.75) -> (99, 18.75)
    point P9 (99, 18.75)
    point P10 (99, 13)
    line L5 (99, 18.75) -> (99, 13)
    point P11 (99, 13)
    point P12 (79.5, 13)
    line L6 (99, 13) -> (79.5, 13)
    point P13 (99, 13)
    point P14 (79.5, 13)
    axis line L7 (99, 13) -> (79.5, 13)
    coincidence: P1 P12, P2 P3, P4 P5, P6 P7, P8 P9, P10 P11
  Groove8: profile Sketch12, axis Sketch12.L7, angle 0, second angle 360
  Sketch13 on Plane13, origin (-13, 0, 0), H (0, 0, -1), V (0, 1, 0)
    point P1 (0, -8.15)
    point P2 (0, -8.8)
    line L1 (0, -8.15) -> (0, -8.8)
    point P3 (0, -8.8)
    point P4 (0.7794, -9.25)
    line L2 (0, -8.8) -> (0.7794, -9.25)
    point P5 (0.7794, -9.25)
    point P6 (4.6, -9.25)
    line L3 (0.7794, -9.25) -> (4.6, -9.25)
    point P7 (4.6, -9.25)
    point P8 (4.6, -10.5)
    line L4 (4.6, -9.25) -> (4.6, -10.5)
    point P9 (4.6, -10.5)
    point P10 (5.033, -10.933)
    line L5 (4.6, -10.5) -> (5.033, -10.933)
    point P11 (5.033, -10.933)
    point P12 (19.5, -10.933)
    line L6 (5.033, -10.933) -> (19.5, -10.933)
    point P13 (19.5, -10.933)
    point P14 (19.5, -8.5)
    line L7 (19.5, -10.933) -> (19.5, -8.5)
    point P15 (19.5, -8.5)
    point P16 (6.5, -8.5)
    line L8 (19.5, -8.5) -> (6.5, -8.5)
    point P17 (6.5, -8.5)
    point P18 (6.5, -7.75)
    line L9 (6.5, -8.5) -> (6.5, -7.75)
    point P19 (6.5, -7.75)
    point P20 (0.4, -7.75)
    line L10 (6.5, -7.75) -> (0.4, -7.75)
    point P21 (0.4, -7.75)
    point P22 (0, -8.15)
    line L11 (0.4, -7.75) -> (0, -8.15)
    point P23 (19.5, -13)
    point P24 (0, -13)
    axis line L12 (19.5, -13) -> (0, -13)
    coincidence: P1 P22, P2 P3, P4 P5, P6 P7, P8 P9, P10 P11, P12 P13, P14 P15, P16 P17, P18 P19, P20 P21
  Shaft3: profile Sketch13, axis Sketch13.L12, angle 0, second angle 360
  Sketch14 on Plane14, origin (-13, 0, 0), H (0, 0, -1), V (0, 1, 0)
    point P1 (79.5, 15.067)
    point P2 (93.967, 15.067)
    line L1 (79.5, 15.067) -> (93.967, 15.067)
    point P3 (93.967, 15.067)
    point P4 (94.4, 15.5)
    line L2 (93.967, 15.067) -> (94.4, 15.5)
    point P5 (94.4, 15.5)
    point P6 (94.4, 16.75)
    line L3 (94.4, 15.5) -> (94.4, 16.75)
    point P7 (94.4, 16.75)
    point P8 (98.2206, 16.75)
    line L4 (94.4, 16.75) -> (98.2206, 16.75)
    point P9 (98.2206, 16.75)
    point P10 (99, 17.2)
    line L5 (98.2206, 16.75) -> (99, 17.2)
    point P11 (99, 17.2)
    point P12 (99, 17.85)
    line L6 (99, 17.2) -> (99, 17.85)
    point P13 (99, 17.85)
    point P14 (98.6, 18.25)
    line L7 (99, 17.85) -> (98.6, 18.25)
    point P15 (98.6, 18.25)
    point P16 (92.5, 18.25)
    line L8 (98.6, 18.25) -> (92.5, 18.25)
    point P17 (92.5, 18.25)
    point P18 (92.5, 17.5)
    line L9 (92.5, 18.25) -> (92.5, 17.5)
    point P19 (92.5, 17.5)
    point P20 (79.5, 17.5)
    line L10 (92.5, 17.5) -> (79.5, 17.5)
    point P21 (79.5, 17.5)
    point P22 (79.5, 15.067)
    line L11 (79.5, 17.5) -> (79.5, 15.067)
    point P23 (99, 13)
    point P24 (79.5, 13)
    axis line L12 (99, 13) -> (79.5, 13)
    coincidence: P1 P22, P2 P3, P4 P5, P6 P7, P8 P9, P10 P11, P12 P13, P14 P15, P16 P17, P18 P19, P20 P21
  Shaft4: profile Sketch14, axis Sketch14.L12, angle 0, second angle 360
  Sketch15 on Plane15, origin (-13, 0, 0), H (0, 0, -1), V (0, 1, 0)
    point P1 (0, 13)
    point P2 (0, 18.75)
    line L1 (0, 13) -> (0, 18.75)
    point P3 (0, 18.75)
    point P4 (6.5, 18.75)
    line L2 (0, 18.75) -> (6.5, 18.75)
    point P5 (6.5, 18.75)
    point P6 (6.5, 16.5)
    line L3 (6.5, 18.75) -> (6.5, 16.5)
    point P7 (6.5, 16.5)
    point P8 (19.5, 16.5)
    line L4 (6.5, 16.5) -> (19.5, 16.5)
    point P9 (19.5, 16.5)
    point P10 (19.5, 13)
    line L5 (19.5, 16.5) -> (19.5, 13)
    point P11 (19.5, 13)
    point P12 (0, 13)
    line L6 (19.5, 13) -> (0, 13)
    point P13 (49.5, 13)
    point P14 (0, 13)
    axis line L7 (49.5, 13) -> (0, 13)
    coincidence: P1 P12, P2 P3, P4 P5, P6 P7, P8 P9, P10 P11
  Groove9: profile Sketch15, axis Sketch15.L7, angle 0, second angle 360
  Sketch16 on Plane16, origin (-13, 0, 0), H (0, 0, -1), V (0, 1, 0)
    point P1 (0, 17.85)
    point P2 (0, 17.2)
    line L1 (0, 17.85) -> (0, 17.2)
    point P3 (0, 17.2)
    point P4 (0.7794, 16.75)
    line L2 (0, 17.2) -> (0.7794, 16.75)
    point P5 (0.7794, 16.75)
    point P6 (4.6, 16.75)
    line L3 (0.7794, 16.75) -> (4.6, 16.75)
    point P7 (4.6, 16.75)
    point P8 (4.6, 15.5)
    line L4 (4.6, 16.75) -> (4.6, 15.5)
    point P9 (4.6, 15.5)
    point P10 (5.033, 15.067)
    line L5 (4.6, 15.5) -> (5.033, 15.067)
    point P11 (5.033, 15.067)
    point P12 (19.5, 15.067)
    line L6 (5.033, 15.067) -> (19.5, 15.067)
    point P13 (19.5, 15.067)
    point P14 (19.5, 17.5)
    line L7 (19.5, 15.067) -> (19.5, 17.5)
    point P15 (19.5, 17.5)
    point P16 (6.5, 17.5)
    line L8 (19.5, 17.5) -> (6.5, 17.5)
    point P17 (6.5, 17.5)
    point P18 (6.5, 18.25)
    line L9 (6.5, 17.5) -> (6.5, 18.25)
    point P19 (6.5, 18.25)
    point P20 (0.4, 18.25)
    line L10 (6.5, 18.25) -> (0.4, 18.25)
    point P21 (0.4, 18.25)
    point P22 (0, 17.85)
    line L11 (0.4, 18.25) -> (0, 17.85)
    point P23 (19.5, 13)
    point P24 (0, 13)
    axis line L12 (19.5, 13) -> (0, 13)
    coincidence: P1 P22, P2 P3, P4 P5, P6 P7, P8 P9, P10 P11, P12 P13, P14 P15, P16 P17, P18 P19, P20 P21
  Shaft5: profile Sketch16, axis Sketch16.L12, angle 0, second angle 360
  Sketch17 on Plane17, origin (13, 0, 0), H (0, 0, -1), V (0, 1, 0)
    point P1 (0, -13)
    point P2 (0, -7.25)
    line L1 (0, -13) -> (0, -7.25)
    point P3 (0, -7.25)
    point P4 (6.5, -7.25)
    line L2 (0, -7.25) -> (6.5, -7.25)
    point P5 (6.5, -7.25)
    point P6 (6.5, -9.5)
    line L3 (6.5, -7.25) -> (6.5, -9.5)
    point P7 (6.5, -9.5)
    point P8 (19.5, -9.5)
    line L4 (6.5, -9.5) -> (19.5, -9.5)
    point P9 (19.5, -9.5)
    point P10 (19.5, -13)
    line L5 (19.5, -9.5) -> (19.5, -13)
    point P11 (19.5, -13)
    point P12 (0, -13)
    line L6 (19.5, -13) -> (0, -13)
    point P13 (19.5, -13)
    point P14 (0, -13)
    axis line L7 (19.5, -13) -> (0, -13)
    coincidence: P1 P12, P2 P3, P4 P5, P6 P7, P8 P9, P10 P11
  Groove10: profile Sketch17, axis Sketch17.L7, angle 0, second angle 360
  Sketch18 on Plane18, origin (13, 0, 0), H (0, 0, -1), V (0, 1, 0)
    point P1 (0, -8.15)
    point P2 (0, -8.8)
    line L1 (0, -8.15) -> (0, -8.8)
    point P3 (0, -8.8)
    point P4 (0.7794, -9.25)
    line L2 (0, -8.8) -> (0.7794, -9.25)
    point P5 (0.7794, -9.25)
    point P6 (4.6, -9.25)
    line L3 (0.7794, -9.25) -> (4.6, -9.25)
    point P7 (4.6, -9.25)
    point P8 (4.6, -10.5)
    line L4 (4.6, -9.25) -> (4.6, -10.5)
    point P9 (4.6, -10.5)
    point P10 (5.033, -10.933)
    line L5 (4.6, -10.5) -> (5.033, -10.933)
    point P11 (5.033, -10.933)
    point P12 (19.5, -10.933)
    line L6 (5.033, -10.933) -> (19.5, -10.933)
    point P13 (19.5, -10.933)
    point P14 (19.5, -8.5)
    line L7 (19.5, -10.933) -> (19.5, -8.5)
    point P15 (19.5, -8.5)
    point P16 (6.5, -8.5)
    line L8 (19.5, -8.5) -> (6.5, -8.5)
    point P17 (6.5, -8.5)
    point P18 (6.5, -7.75)
    line L9 (6.5, -8.5) -> (6.5, -7.75)
    point P19 (6.5, -7.75)
    point P20 (0.4, -7.75)
    line L10 (6.5, -7.75) -> (0.4, -7.75)
    point P21 (0.4, -7.75)
    point P22 (0, -8.15)
    line L11 (0.4, -7.75) -> (0, -8.15)
    point P23 (19.5, -13)
    point P24 (0, -13)
    axis line L12 (19.5, -13) -> (0, -13)
    coincidence: P1 P22, P2 P3, P4 P5, P6 P7, P8 P9, P10 P11, P12 P13, P14 P15, P16 P17, P18 P19, P20 P21
  Shaft6: profile Sketch18, axis Sketch18.L12, angle 0, second angle 360
  Sketch19 on Plane19, origin (-13, 0, 0), H (0, 0, -1), V (0, 1, 0)
    point P1 (79.5, -13)
    point P2 (79.5, -9.5)
    line L1 (79.5, -13) -> (79.5, -9.5)
    point P3 (79.5, -9.5)
    point P4 (92.5, -9.5)
    line L2 (79.5, -9.5) -> (92.5, -9.5)
    point P5 (92.5, -9.5)
    point P6 (92.5, -7.25)
    line L3 (92.5, -9.5) -> (92.5, -7.25)
    point P7 (92.5, -7.25)
    point P8 (99, -7.25)
    line L4 (92.5, -7.25) -> (99, -7.25)
    point P9 (99, -7.25)
    point P10 (99, -13)
    line L5 (99, -7.25) -> (99, -13)
    point P11 (99, -13)
    point P12 (79.5, -13)
    line L6 (99, -13) -> (79.5, -13)
    point P13 (99, -13)
    point P14 (79.5, -13)
    axis line L7 (99, -13) -> (79.5, -13)
    coincidence: P1 P12, P2 P3, P4 P5, P6 P7, P8 P9, P10 P11
  Groove11: profile Sketch19, axis Sketch19.L7, angle 0, second angle 360
  Sketch20 on Plane20, origin (-13, 0, 0), H (0, 0, -1), V (0, 1, 0)
    point P1 (79.5, -10.933)
    point P2 (93.967, -10.933)
    line L1 (79.5, -10.933) -> (93.967, -10.933)
    point P3 (93.967, -10.933)
    point P4 (94.4, -10.5)
    line L2 (93.967, -10.933) -> (94.4, -10.5)
    point P5 (94.4, -10.5)
    point P6 (94.4, -9.25)
    line L3 (94.4, -10.5) -> (94.4, -9.25)
    point P7 (94.4, -9.25)
    point P8 (98.2206, -9.25)
    line L4 (94.4, -9.25) -> (98.2206, -9.25)
    point P9 (98.2206, -9.25)
    point P10 (99, -8.8)
    line L5 (98.2206, -9.25) -> (99, -8.8)
    point P11 (99, -8.8)
    point P12 (99, -8.15)
    line L6 (99, -8.8) -> (99, -8.15)
    point P13 (99, -8.15)
    point P14 (98.6, -7.75)
    line L7 (99, -8.15) -> (98.6, -7.75)
    point P15 (98.6, -7.75)
    point P16 (92.5, -7.75)
    line L8 (98.6, -7.75) -> (92.5, -7.75)
    point P17 (92.5, -7.75)
    point P18 (92.5, -8.5)
    line L9 (92.5, -7.75) -> (92.5, -8.5)
    point P19 (92.5, -8.5)
    point P20 (79.5, -8.5)
    line L10 (92.5, -8.5) -> (79.5, -8.5)
    point P21 (79.5, -8.5)
    point P22 (79.5, -10.933)
    line L11 (79.5, -8.5) -> (79.5, -10.933)
    point P23 (99, -13)
    point P24 (79.5, -13)
    axis line L12 (99, -13) -> (79.5, -13)
    coincidence: P1 P22, P2 P3, P4 P5, P6 P7, P8 P9, P10 P11, P12 P13, P14 P15, P16 P17, P18 P19, P20 P21
  Shaft7: profile Sketch20, axis Sketch20.L12, angle 0, second angle 360
  Sketch21 on Plane21, origin (13, 0, 0), H (0, 0, -1), V (0, 1, 0)
    point P1 (79.5, 13)
    point P2 (79.5, 16.5)
    line L1 (79.5, 13) -> (79.5, 16.5)
    point P3 (79.5, 16.5)
    point P4 (92.5, 16.5)
    line L2 (79.5, 16.5) -> (92.5, 16.5)
    point P5 (92.5, 16.5)
    point P6 (92.5, 18.75)
    line L3 (92.5, 16.5) -> (92.5, 18.75)
    point P7 (92.5, 18.75)
    point P8 (99, 18.75)
    line L4 (92.5, 18.75) -> (99, 18.75)
    point P9 (99, 18.75)
    point P10 (99, 13)
    line L5 (99, 18.75) -> (99, 13)
    point P11 (99, 13)
    point P12 (79.5, 13)
    line L6 (99, 13) -> (79.5, 13)
    point P13 (99, 13)
    point P14 (79.5, 13)
    axis line L7 (99, 13) -> (79.5, 13)
    coincidence: P1 P12, P2 P3, P4 P5, P6 P7, P8 P9, P10 P11
  Groove12: profile Sketch21, axis Sketch21.L7, angle 0, second angle 360
  Sketch22 on Plane22, origin (13, 0, 0), H (0, 0, -1), V (0, 1, 0)
    point P1 (79.5, 15.067)
    point P2 (93.967, 15.067)
    line L1 (79.5, 15.067) -> (93.967, 15.067)
    point P3 (93.967, 15.067)
    point P4 (94.4, 15.5)
    line L2 (93.967, 15.067) -> (94.4, 15.5)
    point P5 (94.4, 15.5)
    point P6 (94.4, 16.75)
    line L3 (94.4, 15.5) -> (94.4, 16.75)
    point P7 (94.4, 16.75)
    point P8 (98.2206, 16.75)
    line L4 (94.4, 16.75) -> (98.2206, 16.75)
    point P9 (98.2206, 16.75)
    point P10 (99, 17.2)
    line L5 (98.2206, 16.75) -> (99, 17.2)
    point P11 (99, 17.2)
    point P12 (99, 17.85)
    line L6 (99, 17.2) -> (99, 17.85)
    point P13 (99, 17.85)
    point P14 (98.6, 18.25)
    line L7 (99, 17.85) -> (98.6, 18.25)
    point P15 (98.6, 18.25)
    point P16 (92.5, 18.25)
    line L8 (98.6, 18.25) -> (92.5, 18.25)
    point P17 (92.5, 18.25)
    point P18 (92.5, 17.5)
    line L9 (92.5, 18.25) -> (92.5, 17.5)
    point P19 (92.5, 17.5)
    point P20 (79.5, 17.5)
    line L10 (92.5, 17.5) -> (79.5, 17.5)
    point P21 (79.5, 17.5)
    point P22 (79.5, 15.067)
    line L11 (79.5, 17.5) -> (79.5, 15.067)
    point P23 (99, 13)
    point P24 (79.5, 13)
    axis line L12 (99, 13) -> (79.5, 13)
    coincidence: P1 P22, P2 P3, P4 P5, P6 P7, P8 P9, P10 P11, P12 P13, P14 P15, P16 P17, P18 P19, P20 P21
  Shaft8: profile Sketch22, axis Sketch22.L12, angle 0, second angle 360
  Sketch23 on Plane23, origin (0, 0, 0), H (1, 0, 0), V (0, 1, 0)
    point P1 (-17.0415, -13)
    point P2 (-16.5, -13.9378)
    line L1 (-17.0415, -13) -> (-16.5, -13.9378)
    point P3 (-16.5, -13.9378)
    point P4 (-16.5, -15.0207)
    line L2 (-16.5, -13.9378) -> (-16.5, -15.0207)
    point P5 (-16.5, -15.0207)
    point P6 (-15.5622, -15.5622)
    line L3 (-16.5, -15.0207) -> (-15.5622, -15.5622)
    point P7 (-15.5622, -15.5622)
    point P8 (-15.0207, -16.5)
    line L4 (-15.5622, -15.5622) -> (-15.0207, -16.5)
    point P9 (-15.0207, -16.5)
    point P10 (-13.9378, -16.5)
    line L5 (-15.0207, -16.5) -> (-13.9378, -16.5)
    point P11 (-13.9378, -16.5)
    point P12 (-13, -17.0415)
    line L6 (-13.9378, -16.5) -> (-13, -17.0415)
    point P13 (-13, -17.0415)
    point P14 (-12.0622, -16.5)
    line L7 (-13, -17.0415) -> (-12.0622, -16.5)
    point P15 (-12.0622, -16.5)
    point P16 (-10.9793, -16.5)
    line L8 (-12.0622, -16.5) -> (-10.9793, -16.5)
    point P17 (-10.9793, -16.5)
    point P18 (-10.4378, -15.5622)
    line L9 (-10.9793, -16.5) -> (-10.4378, -15.5622)
    point P19 (-10.4378, -15.5622)
    point P20 (-9.5, -15.0207)
    line L10 (-10.4378, -15.5622) -> (-9.5, -15.0207)
    point P21 (-9.5, -15.0207)
    point P22 (-9.5, -13.9378)
    line L11 (-9.5, -15.0207) -> (-9.5, -13.9378)
    point P23 (-9.5, -13.9378)
    point P24 (-8.9585, -13)
    line L12 (-9.5, -13.9378) -> (-8.9585, -13)
    point P25 (-8.9585, -13)
    point P26 (-9.5, -12.0622)
    line L13 (-8.9585, -13) -> (-9.5, -12.0622)
    point P27 (-9.5, -12.0622)
    point P28 (-9.5, -10.9793)
    line L14 (-9.5, -12.0622) -> (-9.5, -10.9793)
    point P29 (-9.5, -10.9793)
    point P30 (-10.4378, -10.4378)
    line L15 (-9.5, -10.9793) -> (-10.4378, -10.4378)
    point P31 (-10.4378, -10.4378)
    point P32 (-10.9793, -9.5)
    line L16 (-10.4378, -10.4378) -> (-10.9793, -9.5)
    point P33 (-10.9793, -9.5)
    point P34 (-12.0622, -9.5)
    line L17 (-10.9793, -9.5) -> (-12.0622, -9.5)
    point P35 (-12.0622, -9.5)
    point P36 (-13, -8.9585)
    line L18 (-12.0622, -9.5) -> (-13, -8.9585)
    point P37 (-13, -8.9585)
    point P38 (-13.9378, -9.5)
    line L19 (-13, -8.9585) -> (-13.9378, -9.5)
    point P39 (-13.9378, -9.5)
    point P40 (-15.0207, -9.5)
    line L20 (-13.9378, -9.5) -> (-15.0207, -9.5)
    point P41 (-15.0207, -9.5)
    point P42 (-15.5622, -10.4378)
    line L21 (-15.0207, -9.5) -> (-15.5622, -10.4378)
    point P43 (-15.5622, -10.4378)
    point P44 (-16.5, -10.9793)
    line L22 (-15.5622, -10.4378) -> (-16.5, -10.9793)
    point P45 (-16.5, -10.9793)
    point P46 (-16.5, -12.0622)
    line L23 (-16.5, -10.9793) -> (-16.5, -12.0622)
    point P47 (-16.5, -12.0622)
    point P48 (-17.0415, -13)
    line L24 (-16.5, -12.0622) -> (-17.0415, -13)
    coincidence: P1 P48, P2 P3, P4 P5, P6 P7, P8 P9, P10 P11, P12 P13, P14 P15, P16 P17, P18 P19, P20 P21, P22 P23, P24 P25, P26 P27, P28 P29, P30 P31, P32 P33, P34 P35, P36 P37, P38 P39, P40 P41, P42 P43, P44 P45, P46 P47
  Pocket2: profile Sketch23, direction (0, 0, -1), length 4.4
  Sketch24 on Plane24, origin (0, 0, 0), H (1, 0, 0), V (0, 1, 0)
    point P1 (-17.0415, 13)
    point P2 (-16.5, 12.0622)
    line L1 (-17.0415, 13) -> (-16.5, 12.0622)
    point P3 (-16.5, 12.0622)
    point P4 (-16.5, 10.9793)
    line L2 (-16.5, 12.0622) -> (-16.5, 10.9793)
    point P5 (-16.5, 10.9793)
    point P6 (-15.5622, 10.4378)
    line L3 (-16.5, 10.9793) -> (-15.5622, 10.4378)
    point P7 (-15.5622, 10.4378)
    point P8 (-15.0207, 9.5)
    line L4 (-15.5622, 10.4378) -> (-15.0207, 9.5)
    point P9 (-15.0207, 9.5)
    point P10 (-13.9378, 9.5)
    line L5 (-15.0207, 9.5) -> (-13.9378, 9.5)
    point P11 (-13.9378, 9.5)
    point P12 (-13, 8.9585)
    line L6 (-13.9378, 9.5) -> (-13, 8.9585)
    point P13 (-13, 8.9585)
    point P14 (-12.0622, 9.5)
    line L7 (-13, 8.9585) -> (-12.0622, 9.5)
    point P15 (-12.0622, 9.5)
    point P16 (-10.9793, 9.5)
    line L8 (-12.0622, 9.5) -> (-10.9793, 9.5)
